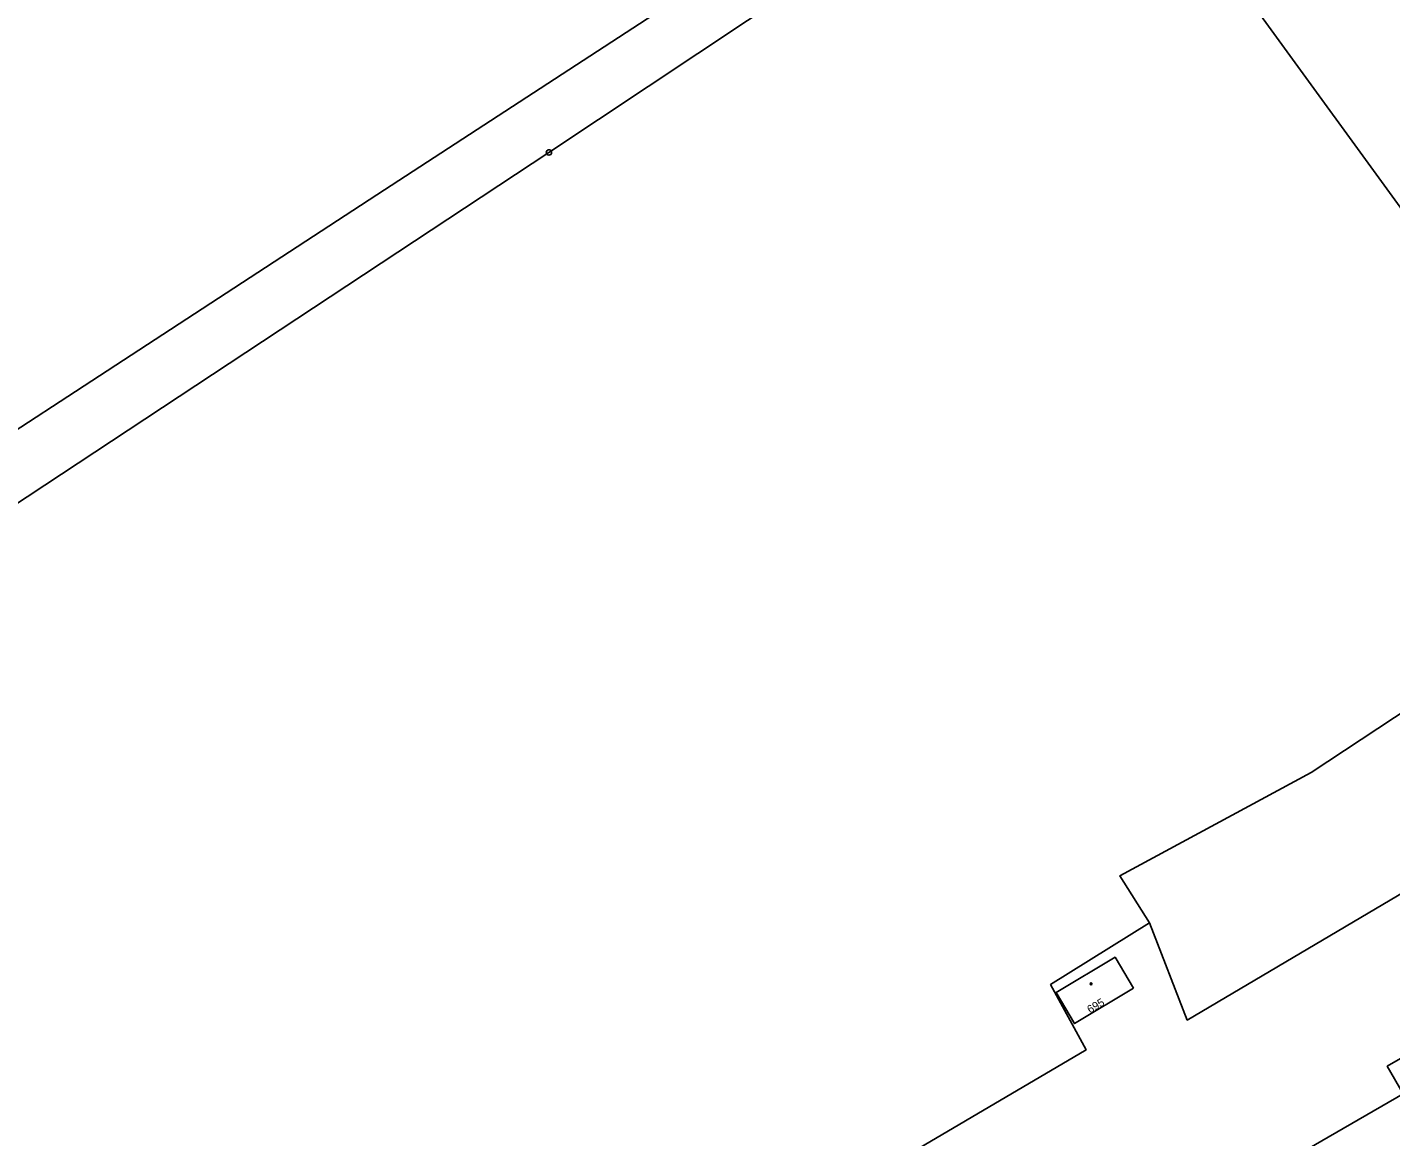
# Model space of a CAD drawing. Extents: x -504988 to -494607, y -1123820 to -1114018.
# Drawn here: x -497544 to -497288.4, y -1120850 to -1120642 of the extents above; entities that cross this region are included whole.
import ezdxf

# ---------------------------------------------------------------- set-up
doc = ezdxf.new("R2010")
doc.units = 0
for name, color, linetype in [('Hranice parcel', 7, 'Continuous'), ('Parcelní čísla', 7, 'Continuous'), ('Značky bodu BP', 7, 'Continuous'), ('Značky budov', 7, 'Continuous')]:
    doc.layers.add(name, color=color, linetype=linetype)

msp = doc.modelspace()

# ---------------------------------------------------------------- linework, layer by layer
at = {"layer": 'Hranice parcel'}
msp.add_line((-497343.59, -1120597.23), (-497244.66, -1120733.63), dxfattribs=at)
for points in [[(-497349.37, -1120589.26), (-497477.01, -1120672.48), (-497604.63, -1120755.71), (-497698.4, -1120816.44), (-497821.04, -1120898.04), (-497931.33, -1120969.32), (-498041.62, -1121040.59), (-498124.46, -1121095.39), (-498243.47, -1121172.51), (-498264.79, -1121187.65), (-498296.3, -1121208.05), (-498309.12, -1121214.61), (-498319.07, -1121213.07), (-498324.96, -1121206.38)], [(-497343.59, -1120597.23), (-497446.2, -1120665.45), (-497531.34, -1120721.63), (-497616.47, -1120777.81), (-497720.15, -1120845.42), (-497823.83, -1120913.02), (-497984.58, -1121017.48), (-498052.05, -1121061.59), (-498108.05, -1121098.26)], [(-497333.61, -1120809.89), (-497326.54, -1120828.14), (-497233.31, -1120773.05), (-497224.84, -1120767.5), (-497195.09, -1120751.17), (-497182.47, -1120749.46), (-497152.39, -1120732.45), (-497124.03, -1120713.08), (-497125.53, -1120710.19)], [(-497265.99, -1120757.11), (-497303.31, -1120781.72), (-497339.16, -1120801.08), (-497333.61, -1120809.89)], [(-497555.98, -1120992.84), (-497537.12, -1120979.41), (-497518.33, -1120963.79), (-497480.69, -1120928.77), (-497423.69, -1120882.7), (-497390.75, -1120860.31), (-497345.49, -1120833.73), (-497352.15, -1120821.47), (-497333.61, -1120809.89)], [(-497336.59, -1120822.18), (-497340.07, -1120816.34), (-497351.14, -1120822.94), (-497347.66, -1120828.78), (-497336.59, -1120822.18)], [(-497270.83, -1120826.31), (-497289.04, -1120836.8), (-497286.05, -1120841.99), (-497329.02, -1120866.76), (-497324.47, -1120874.67), (-497263.28, -1120839.39)]]:
    msp.add_lwpolyline(points, dxfattribs=at)
at = {"layer": 'Značky bodu BP'}
for radius in [0.5, 0.0303]:
    msp.add_circle((-497446.2, -1120665.45), radius, dxfattribs=at)
at = {"layer": 'Značky budov'}
msp.add_circle((-497344.57, -1120821.34), 0.175, dxfattribs=at)

# ---------------------------------------------------------------- texts
at = {"layer": 'Parcelní čísla'}
msp.add_text('695', height=1.5, rotation=31, dxfattribs=at).set_placement((-497344.75, -1120826.95))

doc.saveas('drawing.dxf')
